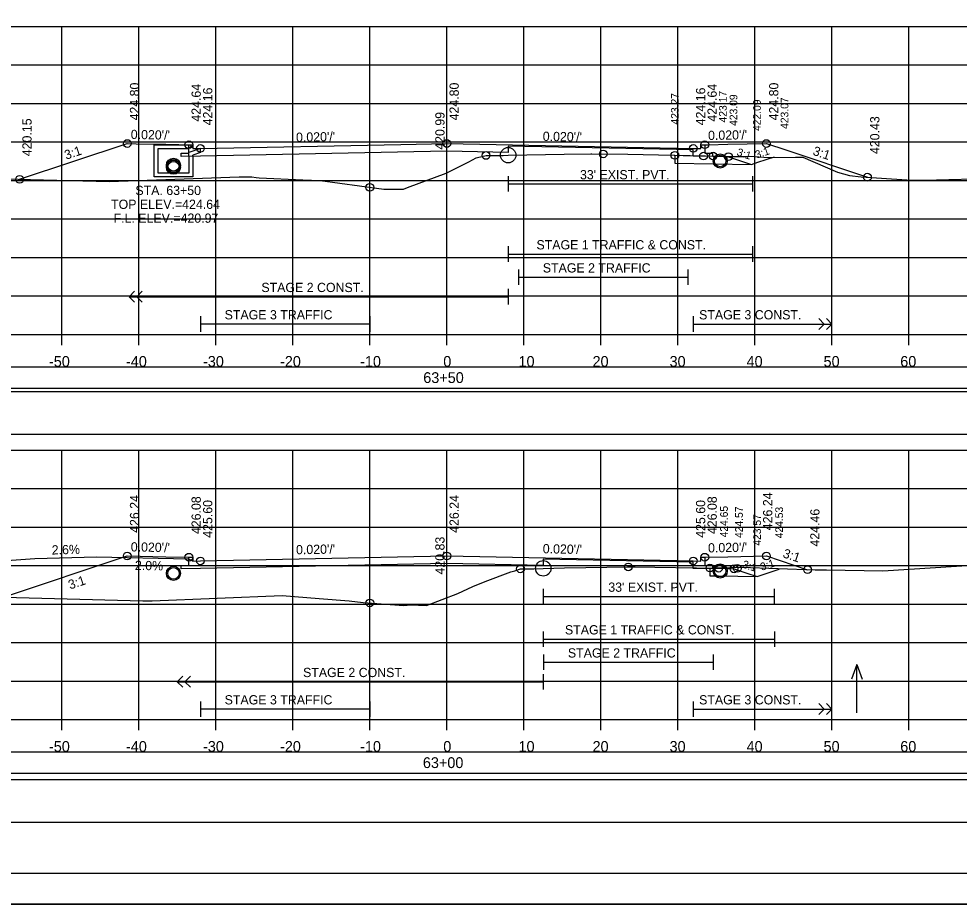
# Model space of a CAD drawing. Extents: x 1371057 to 1372761, y 380005 to 390517.
# Drawn here: x 1371505.3 to 1371627.4, y 385125.2 to 385240.2 of the extents above; entities that cross this region are included whole.
import ezdxf

# ---------------------------------------------------------------- set-up
doc = ezdxf.new("R2010")
doc.units = 0
for name, color, linetype in [('R_Alt Surface', 7, 'Continuous'), ('R_Axis', 7, 'Continuous'), ('R_Axis Annot', 7, 'Continuous'), ('R_Border', 7, 'Continuous'), ('R_Detour', 7, 'Continuous'), ('R_Draft', 7, 'Continuous'), ('R_Drive', 7, 'Continuous'), ('R_Exist Surface', 7, 'Continuous'), ('R_Fin Surface', 7, 'Continuous'), ('R_Fin Surface Annot', 7, 'Continuous'), ('R_Grid', 7, 'Continuous'), ('R_No Plot', 7, 'Continuous'), ('R_Striping', 7, 'Continuous'), ('R_Water', 7, 'Continuous'), ('R_Water Annot', 7, 'Continuous'), ('R_Xsect Elev', 7, 'Continuous'), ('R_Xsect Slope', 7, 'Continuous')]:
    doc.layers.add(name, color=color, linetype=linetype)

msp = doc.modelspace()

# ---------------------------------------------------------------- linework, layer by layer
at = {"layer": 'R_Alt Surface'}
for points in [[(1371594.37, 385223.81), (1371594.37, 385222.73), (1371595.37, 385222.71), (1371595.37, 385222.28), (1371592.87, 385222.33), (1371592.87, 385222.33), (1371592.87, 385223.16), (1371568.84, 385223.64), (1371568.84, 385222.81), (1371560.87, 385222.97), (1371528.87, 385222.33), (1371526.37, 385222.28), (1371526.37, 385222.71), (1371527.37, 385222.73), (1371527.37, 385223.81)], [(1371568.84, 385219.72), (1371568.84, 385217.72)], [(1371568.84, 385218.72), (1371600.58, 385218.72)], [(1371600.58, 385219.72), (1371600.58, 385217.72)], [(1371594.37, 385170.25), (1371594.37, 385169.17), (1371595.37, 385169.15), (1371595.37, 385168.72), (1371592.87, 385168.77), (1371592.87, 385168.77), (1371592.87, 385169.6), (1371573.39, 385169.99), (1371573.39, 385169.16), (1371560.87, 385169.41), (1371528.87, 385168.77), (1371526.37, 385168.72), (1371526.37, 385169.15), (1371527.37, 385169.17), (1371527.37, 385170.25)], [(1371573.39, 385166.15), (1371573.39, 385164.16)], [(1371603.39, 385166.16), (1371603.39, 385164.16)], [(1371573.39, 385165.16), (1371603.39, 385165.16)]]:
    msp.add_lwpolyline(points, dxfattribs=at)
at = {"layer": 'R_Axis'}
for p, q in [((1371410.87, 385199.17), (1371710.87, 385199.17)), ((1371510.87, 385197.77), (1371510.87, 385199.17)), ((1371520.87, 385197.77), (1371520.87, 385199.17)), ((1371530.87, 385197.77), (1371530.87, 385199.17)), ((1371540.87, 385197.77), (1371540.87, 385199.17)), ((1371550.87, 385197.77), (1371550.87, 385199.17)), ((1371560.87, 385197.77), (1371560.87, 385199.17)), ((1371570.87, 385197.77), (1371570.87, 385199.17)), ((1371580.87, 385197.77), (1371580.87, 385199.17)), ((1371590.87, 385197.77), (1371590.87, 385199.17)), ((1371600.87, 385197.77), (1371600.87, 385199.17)), ((1371610.87, 385197.77), (1371610.87, 385199.17)), ((1371620.87, 385197.77), (1371620.87, 385199.17)), ((1371410.87, 385149.17), (1371710.87, 385149.17)), ((1371510.87, 385147.77), (1371510.87, 385149.17)), ((1371520.87, 385147.77), (1371520.87, 385149.17)), ((1371530.87, 385147.77), (1371530.87, 385149.17)), ((1371540.87, 385147.77), (1371540.87, 385149.17)), ((1371550.87, 385147.77), (1371550.87, 385149.17)), ((1371560.87, 385147.77), (1371560.87, 385149.17)), ((1371570.87, 385147.77), (1371570.87, 385149.17)), ((1371580.87, 385147.77), (1371580.87, 385149.17)), ((1371590.87, 385147.77), (1371590.87, 385149.17)), ((1371600.87, 385147.77), (1371600.87, 385149.17)), ((1371610.87, 385147.77), (1371610.87, 385149.17)), ((1371620.87, 385147.77), (1371620.87, 385149.17))]:
    msp.add_line(p, q, dxfattribs=at)
at = {"layer": 'R_Border'}
msp.add_line((1371719.05, 385129.17), (1371402.87, 385129.17), dxfattribs=at)
at = {"layer": 'R_Detour'}
for points in [[(1371590.48, 385222.44), (1371591.56, 385222.42), (1371595.44, 385222.34), (1371596.95, 385222.28), (1371597.44, 385222.26), (1371599.65, 385221.52), (1371600.44, 385221.26), (1371601.25, 385221.53), (1371603.4, 385222.24)], [(1371590.48, 385222.44), (1371590.48, 385221.44), (1371595.44, 385221.34), (1371600.44, 385221.26)], [(1371595.03, 385168.84), (1371595.62, 385168.83), (1371596.16, 385168.82), (1371597.23, 385168.78), (1371598.16, 385168.74), (1371599.84, 385168.18), (1371601.16, 385167.74), (1371602.35, 385168.14), (1371604.02, 385168.7)], [(1371595.03, 385168.84), (1371595.03, 385167.84), (1371596.16, 385167.82), (1371601.16, 385167.74)]]:
    msp.add_lwpolyline(points, dxfattribs=at)
for points in [[(1371407.72, 385192.22), (1371714.03, 385192.22), (1371714.03, 385194.92), (1371407.72, 385194.92)], [(1371407.72, 385142.22), (1371714.03, 385142.22), (1371714.03, 385144.92), (1371407.72, 385144.92)]]:
    msp.add_lwpolyline(points, close=True, dxfattribs=at)
at = {"layer": 'R_Draft'}
for points in [[(1371407.45, 385186.22), (1371713.76, 385186.22), (1371713.76, 385191.74), (1371407.45, 385191.74)], [(1371407.45, 385135.83), (1371713.76, 385135.83), (1371713.76, 385141.35), (1371407.45, 385141.35)]]:
    msp.add_lwpolyline(points, close=True, dxfattribs=at)
at = {"layer": 'R_Drive'}
for p, q in [((1371507.38, 385170.03), (1371499.4, 385169.46)), ((1371515.38, 385170.24), (1371507.38, 385170.03)), ((1371527.38, 385170), (1371515.38, 385170.24)), ((1371527.88, 385169.75), (1371527.38, 385170))]:
    msp.add_line(p, q, dxfattribs=at)
at = {"layer": 'R_Exist Surface'}
for points in [[(1371602.63, 385222.17), (1371606.16, 385222.19), (1371607.11, 385222.19), (1371611.59, 385220.25), (1371613.17, 385219.81), (1371614.65, 385219.66), (1371620.59, 385219.25), (1371622.82, 385219.22), (1371629.29, 385219.4), (1371632.05, 385220.24), (1371633.41, 385220.67), (1371640.68, 385222.44), (1371641.48, 385222.61), (1371641.86, 385222.7), (1371642.14, 385222.77), (1371642.78, 385222.77), (1371650.96, 385224.38), (1371658.47, 385224.69), (1371659.09, 385224.72), (1371660.66, 385224.2), (1371679.54, 385218.13), (1371690.67, 385213.78), (1371698.17, 385210.89), (1371710.87, 385211.41)], [(1371495.46, 385219.59), (1371506.81, 385219.28), (1371517.02, 385219.04), (1371523.15, 385219.26), (1371533.92, 385219.65), (1371535.53, 385219.66), (1371536.1, 385219.54), (1371536.48, 385219.53), (1371542.19, 385219.26), (1371544.42, 385219.18), (1371549.51, 385218.46), (1371552.68, 385218.04), (1371555.13, 385218.05), (1371555.26, 385218.05), (1371555.75, 385218.24), (1371560.79, 385220.12), (1371563.72, 385221.59), (1371564.66, 385222.09), (1371564.87, 385222.14), (1371565.96, 385222.42), (1371568.2, 385222.43), (1371568.84, 385222.46), (1371568.84, 385222.46), (1371576.11, 385222.59), (1371579.55, 385222.65), (1371579.69, 385222.64), (1371584.39, 385222.57), (1371588.37, 385222.49), (1371590.41, 385222.44), (1371590.48, 385222.44), (1371594.46, 385222.35), (1371597.49, 385222.29), (1371598.66, 385222.28), (1371599.33, 385222.29), (1371599.79, 385222.3), (1371600.12, 385222.31), (1371602.63, 385222.17)], [(1371498.4, 385165.18), (1371521.41, 385164.58), (1371521.98, 385164.57), (1371522.6, 385164.59), (1371539.49, 385165.26), (1371544.31, 385164.88), (1371548.2, 385164.57), (1371550, 385164.38), (1371555.3, 385163.98), (1371556.15, 385164.05), (1371558.23, 385163.96), (1371562.29, 385165.55), (1371564.26, 385166.45), (1371565.84, 385167.08), (1371569.19, 385168.37), (1371569.7, 385168.5), (1371570.43, 385168.73), (1371572.16, 385168.76), (1371573.39, 385168.8), (1371576.17, 385168.87), (1371578.9, 385168.93), (1371581.66, 385168.96), (1371584.33, 385168.99), (1371584.8, 385168.99), (1371585.33, 385169), (1371587.86, 385168.97), (1371593.31, 385168.88), (1371595.03, 385168.84), (1371595.96, 385168.85), (1371597.77, 385168.9), (1371599.07, 385168.95), (1371608.71, 385168.61)], [(1371608.71, 385168.61), (1371610.18, 385168.63), (1371617.47, 385168.49), (1371630.48, 385169.28), (1371631.66, 385169.24), (1371633.04, 385169.17), (1371638.13, 385168.94), (1371647.78, 385168.58), (1371650.08, 385168.63), (1371655.66, 385169.36), (1371656.54, 385169.38), (1371660.65, 385169.25), (1371661.37, 385169.24), (1371663.65, 385169.3), (1371667.81, 385169.06), (1371671.71, 385169.15), (1371676.71, 385168.26), (1371691.54, 385164.97), (1371697.83, 385163.65), (1371700.11, 385163.72), (1371710.87, 385164.54)]]:
    msp.add_lwpolyline(points, dxfattribs=at)
at = {"layer": 'R_Fin Surface'}
for points in [[(1371505.4, 385219.32), (1371519.37, 385223.97), (1371520.53, 385223.95), (1371524.37, 385223.87), (1371526.08, 385223.84), (1371527.37, 385223.81), (1371527.87, 385223.81), (1371527.88, 385223.31), (1371528.25, 385223.32), (1371528.87, 385223.33), (1371528.87, 385223.33), (1371554.9, 385223.85), (1371560.87, 385223.97), (1371592.87, 385223.33), (1371593.78, 385223.31), (1371593.87, 385223.31), (1371593.87, 385223.81), (1371594.37, 385223.81), (1371594.87, 385223.82), (1371597.37, 385223.87), (1371602.37, 385223.97), (1371604.91, 385223.13), (1371615.49, 385219.6)], [(1371503.31, 385165.06), (1371519.37, 385170.41), (1371524.37, 385170.31), (1371527.37, 385170.25), (1371527.53, 385170.25), (1371527.87, 385170.25), (1371527.88, 385169.75), (1371528.87, 385169.77), (1371560.87, 385170.41), (1371560.87, 385170.41), (1371560.87, 385170.41), (1371592.87, 385169.77), (1371593.87, 385169.75), (1371593.87, 385170.25), (1371593.97, 385170.25), (1371594.37, 385170.25), (1371597.37, 385170.31), (1371602.37, 385170.41), (1371607.71, 385168.63)]]:
    msp.add_lwpolyline(points, dxfattribs=at)
at = {"layer": 'R_Grid'}
for p, q in [((1371410.87, 385239.17), (1371710.87, 385239.17)), ((1371510.87, 385199.17), (1371510.87, 385239.17)), ((1371520.87, 385199.17), (1371520.87, 385239.17)), ((1371530.87, 385199.17), (1371530.87, 385239.17)), ((1371540.87, 385199.17), (1371540.87, 385239.17)), ((1371550.87, 385199.17), (1371550.87, 385239.17)), ((1371560.87, 385199.17), (1371560.87, 385239.17)), ((1371570.87, 385199.17), (1371570.87, 385239.17)), ((1371580.87, 385199.17), (1371580.87, 385239.17)), ((1371590.87, 385199.17), (1371590.87, 385239.17)), ((1371600.87, 385199.17), (1371600.87, 385239.17)), ((1371610.87, 385199.17), (1371610.87, 385239.17)), ((1371620.87, 385199.17), (1371620.87, 385239.17)), ((1371410.87, 385234.17), (1371710.87, 385234.17)), ((1371410.87, 385229.17), (1371710.87, 385229.17)), ((1371410.87, 385224.17), (1371710.87, 385224.17)), ((1371410.87, 385219.17), (1371710.87, 385219.17)), ((1371410.87, 385214.17), (1371710.87, 385214.17)), ((1371410.87, 385209.17), (1371710.87, 385209.17)), ((1371410.87, 385204.17), (1371710.87, 385204.17)), ((1371410.87, 385199.17), (1371710.87, 385199.17)), ((1371410.87, 385184.17), (1371710.87, 385184.17)), ((1371510.87, 385149.17), (1371510.87, 385184.17)), ((1371520.87, 385149.17), (1371520.87, 385184.17)), ((1371530.87, 385149.17), (1371530.87, 385184.17)), ((1371540.87, 385149.17), (1371540.87, 385184.17)), ((1371550.87, 385149.17), (1371550.87, 385184.17)), ((1371560.87, 385149.17), (1371560.87, 385184.17)), ((1371570.87, 385149.17), (1371570.87, 385184.17)), ((1371580.87, 385149.17), (1371580.87, 385184.17)), ((1371590.87, 385149.17), (1371590.87, 385184.17)), ((1371600.87, 385149.17), (1371600.87, 385184.17)), ((1371610.87, 385149.17), (1371610.87, 385184.17)), ((1371620.87, 385149.17), (1371620.87, 385184.17)), ((1371410.87, 385179.17), (1371710.87, 385179.17)), ((1371410.87, 385174.17), (1371710.87, 385174.17)), ((1371410.87, 385169.17), (1371710.87, 385169.17)), ((1371410.87, 385164.17), (1371710.87, 385164.17)), ((1371410.87, 385159.17), (1371710.87, 385159.17)), ((1371410.87, 385154.17), (1371710.87, 385154.17)), ((1371410.87, 385149.17), (1371710.87, 385149.17))]:
    msp.add_line(p, q, dxfattribs=at)
at = {"layer": 'R_No Plot'}
msp.add_line((1371390.47, 385125.19), (1371723.8, 385125.19), dxfattribs=at)
for points in [[(1371390.46, 385338.53), (1371723.8, 385338.53), (1371723.8, 385125.19), (1371390.46, 385125.19)], [(1371636.79, 385334.63), (1371656.41, 385334.63), (1371656.41, 385324.75), (1371672.52, 385324.75), (1371695.72, 385324.75), (1371695.84, 385296.59), (1371719.05, 385296.59), (1371719.05, 385129.17), (1371402.87, 385129.17), (1371402.87, 385334.63)]]:
    msp.add_lwpolyline(points, close=True, dxfattribs=at)
for centre, radius in [((1371519.37, 385223.97), 0.5), ((1371527.37, 385223.81), 0.5), ((1371528.87, 385223.33), 0.5), ((1371560.87, 385223.97), 0.5), ((1371592.87, 385223.33), 0.5), ((1371594.37, 385223.81), 0.5), ((1371602.37, 385223.97), 0.5), ((1371565.96, 385222.42), 0.5), ((1371568.84, 385222.46), 1), ((1371581.18, 385222.62), 0.5), ((1371590.48, 385222.44), 0.5), ((1371594.2, 385222.34), 0.5), ((1371595.44, 385222.34), 0.5), ((1371596.37, 385221.7), 0.917), ((1371597.44, 385222.26), 0.5), ((1371525.37, 385221.14), 0.917), ((1371525.37, 385220.89), 0.917), ((1371615.49, 385219.6), 0.5), ((1371505.4, 385219.32), 0.5), ((1371550.87, 385218.28), 0.5), ((1371519.37, 385170.41), 0.5), ((1371527.37, 385170.25), 0.5), ((1371528.87, 385169.77), 0.5), ((1371560.87, 385170.41), 0.5), ((1371592.87, 385169.77), 0.5), ((1371594.37, 385170.25), 0.5), ((1371602.37, 385170.41), 0.5), ((1371525.37, 385168.15), 0.917), ((1371570.43, 385168.73), 0.5), ((1371573.39, 385168.8), 1), ((1371584.44, 385168.99), 0.5), ((1371595.03, 385168.84), 0.5), ((1371596.37, 385168.45), 0.917), ((1371596.16, 385168.82), 0.5), ((1371598.16, 385168.74), 0.5), ((1371598.59, 385168.79), 0.5), ((1371607.71, 385168.63), 0.5), ((1371550.87, 385164.31), 0.5)]:
    msp.add_circle(centre, radius, dxfattribs=at)
at = {"layer": 'R_Striping'}
for p, q in [((1371568.84, 385210.62), (1371568.84, 385208.62)), ((1371600.58, 385210.62), (1371600.58, 385208.62)), ((1371568.84, 385209.62), (1371600.58, 385209.62)), ((1371570.18, 385207.62), (1371570.18, 385205.62)), ((1371570.18, 385206.62), (1371592.18, 385206.62)), ((1371592.18, 385207.62), (1371592.18, 385205.62)), ((1371519.6, 385204.08), (1371520.31, 385204.78)), ((1371519.6, 385204.08), (1371568.84, 385204.08)), ((1371520.31, 385203.37), (1371519.6, 385204.08)), ((1371520.6, 385204.08), (1371521.31, 385204.78)), ((1371521.31, 385203.37), (1371520.6, 385204.08)), ((1371568.84, 385205.08), (1371568.84, 385203.08)), ((1371528.87, 385201.53), (1371528.87, 385199.53)), ((1371550.87, 385200.53), (1371528.87, 385200.53)), ((1371550.87, 385201.53), (1371550.87, 385199.53)), ((1371592.87, 385201.53), (1371592.87, 385199.53)), ((1371592.87, 385200.53), (1371610.87, 385200.53)), ((1371609.87, 385200.53), (1371609.17, 385201.24)), ((1371609.17, 385199.83), (1371609.87, 385200.53)), ((1371610.87, 385200.53), (1371610.17, 385201.24)), ((1371610.17, 385199.83), (1371610.87, 385200.53)), ((1371573.39, 385160.62), (1371573.39, 385158.62)), ((1371603.42, 385160.62), (1371603.42, 385158.62)), ((1371573.39, 385159.62), (1371603.42, 385159.62)), ((1371573.44, 385157.62), (1371573.44, 385155.62)), ((1371595.44, 385157.62), (1371595.44, 385155.62)), ((1371573.44, 385156.62), (1371595.44, 385156.62)), ((1371525.87, 385154.08), (1371526.57, 385154.78)), ((1371525.87, 385154.08), (1371573.39, 385154.08)), ((1371526.57, 385153.37), (1371525.87, 385154.08)), ((1371526.87, 385154.08), (1371527.57, 385154.78)), ((1371527.57, 385153.37), (1371526.87, 385154.08)), ((1371573.39, 385155.08), (1371573.39, 385153.08)), ((1371528.87, 385151.53), (1371528.87, 385149.53)), ((1371550.87, 385151.53), (1371550.87, 385149.53)), ((1371592.87, 385151.53), (1371592.87, 385149.53)), ((1371550.87, 385150.53), (1371528.87, 385150.53)), ((1371592.87, 385150.53), (1371610.87, 385150.53)), ((1371609.87, 385150.53), (1371609.17, 385151.24)), ((1371609.17, 385149.83), (1371609.87, 385150.53)), ((1371610.87, 385150.53), (1371610.17, 385151.24)), ((1371610.17, 385149.83), (1371610.87, 385150.53))]:
    msp.add_line(p, q, dxfattribs=at)
at = {"layer": 'R_Water'}
for p, q in [((1371522.87, 385223.81), (1371527.62, 385223.81)), ((1371522.87, 385222.31), (1371522.87, 385223.81)), ((1371527.7, 385223.65), (1371527.37, 385223.31)), ((1371527.7, 385223.65), (1371527.62, 385223.81)), ((1371523.37, 385222.31), (1371523.37, 385223.31)), ((1371523.37, 385223.31), (1371527.37, 385223.31)), ((1371528.87, 385223.33), (1371527.37, 385222.81)), ((1371527.37, 385222.31), (1371527.37, 385222.81)), ((1371528.87, 385222.8), (1371527.87, 385222.46)), ((1371527.87, 385222.31), (1371527.87, 385222.46))]:
    msp.add_line(p, q, dxfattribs=at)
for points in [[(1371528.87, 385222.8), (1371528.87, 385223.33)], [(1371527.87, 385222.31), (1371527.87, 385219.64), (1371525.37, 385219.64), (1371522.87, 385219.64), (1371522.87, 385222.31)], [(1371527.37, 385222.31), (1371527.37, 385220.14), (1371525.37, 385220.14), (1371523.37, 385220.14), (1371523.37, 385222.31)]]:
    msp.add_lwpolyline(points, dxfattribs=at)
for centre in [(1371596.37, 385221.7), (1371525.37, 385221.14), (1371525.37, 385220.89), (1371525.37, 385168.15), (1371596.37, 385168.45)]:
    msp.add_circle(centre, 0.75, dxfattribs=at)
at = {"layer": 'R_Water Annot'}
for p, q in [((1371614.11, 385156.32), (1371613.41, 385154.4)), ((1371614.11, 385150.04), (1371614.11, 385156.32)), ((1371614.11, 385156.32), (1371614.81, 385154.4))]:
    msp.add_line(p, q, dxfattribs=at)
at = {"layer": 'R_Xsect Elev'}
for p, q in [((1371560.87, 385220.16), (1371560.87, 385230.16)), ((1371560.87, 385165), (1371560.87, 385175))]:
    msp.add_line(p, q, dxfattribs=at)

# ---------------------------------------------------------------- texts
at = {"layer": 'R_Axis Annot'}
for s, p in [('-50', (1371509.21, 385194.97)), ('-40', (1371519.21, 385194.97)), ('-30', (1371529.21, 385194.97)), ('-20', (1371539.21, 385194.97)), ('-10', (1371549.61, 385194.97)), ('0', (1371560.41, 385194.97)), ('10', (1371570.18, 385194.97)), ('20', (1371579.79, 385194.97)), ('30', (1371589.79, 385194.97)), ('40', (1371599.79, 385194.97)), ('50', (1371609.79, 385194.97)), ('60', (1371619.75, 385194.97)), ('63+50', (1371557.81, 385192.87)), ('-50', (1371509.21, 385144.97)), ('-40', (1371519.21, 385144.97)), ('-30', (1371529.21, 385144.97)), ('-20', (1371539.21, 385144.97)), ('-10', (1371549.61, 385144.97)), ('0', (1371560.41, 385144.97)), ('10', (1371570.18, 385144.97)), ('20', (1371579.79, 385144.97)), ('30', (1371589.79, 385144.97)), ('40', (1371599.79, 385144.97)), ('50', (1371609.79, 385144.97)), ('60', (1371619.75, 385144.97)), ('63+00', (1371557.76, 385142.87))]:
    msp.add_text(s, height=1.4, dxfattribs=at).set_placement(p)
at = {"layer": 'R_Fin Surface Annot'}
for s, rotation, p in [('423.27', 90, (1371590.98, 385226.44)), ('423.17', 90, (1371597.21, 385226.71)), ('423.09', 90, (1371598.59, 385226.26)), ('423.07', 90, (1371605.22, 385225.87)), ('422.09', 90, (1371601.64, 385225.6)), ('3:1', 341.546, (1371598.44, 385222.45)), ('3:1', 18.407, (1371601.1, 385222.01)), ('424.65', 90, (1371597.36, 385172.82)), ('424.57', 90, (1371599.31, 385172.74)), ('424.53', 90, (1371604.52, 385172.7)), ('423.57', 90, (1371601.66, 385171.74)), ('3:1', 341.6649, (1371599.16, 385168.93)), ('3:1', 18.497, (1371601.77, 385168.48))]:
    msp.add_text(s, height=1, rotation=rotation, dxfattribs=at).set_placement(p)
at = {"layer": 'R_Striping'}
for s, p in [('STAGE 1 TRAFFIC & CONST.', (1371572.51, 385210.22)), ('STAGE 2 TRAFFIC', (1371573.33, 385207.22)), ('STAGE 2 CONST.', (1371536.79, 385204.68)), ('STAGE 3 TRAFFIC', (1371532.02, 385201.13)), ('STAGE 3 CONST.', (1371593.63, 385201.13)), ('STAGE 1 TRAFFIC & CONST.', (1371576.21, 385160.22)), ('STAGE 2 TRAFFIC', (1371576.59, 385157.22)), ('STAGE 2 CONST.', (1371542.2, 385154.68)), ('STAGE 3 TRAFFIC', (1371532.02, 385151.13)), ('STAGE 3 CONST.', (1371593.63, 385151.13))]:
    msp.add_text(s, height=1.2, dxfattribs=at).set_placement(p)
at = {"layer": 'R_Water'}
for p in [(1371578.16, 385219.32), (1371581.84, 385165.76)]:
    msp.add_text("33' EXIST. PVT.", height=1.2, dxfattribs=at).set_placement(p)
at = {"layer": 'R_Water Annot'}
for s, p in [('STA. 63+50', (1371520.43, 385217.28)), ('TOP ELEV.=424.64', (1371517.27, 385215.48)), ('F.L. ELEV.=420.97', (1371517.6, 385213.68))]:
    msp.add_text(s, height=1.2, dxfattribs=at).set_placement(p)
at = {"layer": 'R_Xsect Elev'}
for s, rotation, p in [('424.80', 90, (1371520.92, 385226.97)), ('424.64', 90, (1371528.92, 385226.81)), ('424.16', 90, (1371530.42, 385226.33)), ('424.80', 90, (1371562.42, 385226.97)), ('424.16', 90, (1371594.42, 385226.33)), ('424.64', 90, (1371595.92, 385226.81)), ('424.80', 90, (1371603.92, 385226.97)), ('420.99', 90, (1371560.57, 385223.16)), ('420.43', 90, (1371617.04, 385222.6)), ('420.15', 90, (1371506.95, 385222.32)), ('426.24', 90, (1371603.13, 385173.75)), ('426.24', 90, (1371520.92, 385173.41)), ('426.08', 90, (1371528.92, 385173.25)), ('425.60', 90, (1371530.42, 385172.77)), ('426.24', 90, (1371562.42, 385173.41)), ('425.60', 90, (1371594.42, 385172.77)), ('426.08', 90, (1371595.92, 385173.25)), ('424.46', 90, (1371609.26, 385171.63)), ('420.83', 90, (1371560.57, 385168)), ('2.6%', 1.4894, (1371509.58, 385170.59)), ('2.0%', 358.8542, (1371520.36, 385168.6))]:
    msp.add_text(s, height=1.2, rotation=rotation, dxfattribs=at).set_placement(p)
at = {"layer": 'R_Xsect Slope'}
for s, rotation, p in [("0.020'/'", 358.8543, (1371519.82, 385224.56)), ("0.020'/'", 1.1458, (1371541.3, 385224.18)), ("0.020'/'", 358.8542, (1371573.32, 385224.32)), ("0.020'/'", 1.1457, (1371594.8, 385224.42)), ('3:1', 18.4321, (1371511.44, 385221.86)), ('3:1', 341.5644, (1371608.3, 385222.52)), ("0.020'/'", 358.8541, (1371519.82, 385171)), ("0.020'/'", 1.1458, (1371541.3, 385170.62)), ("0.020'/'", 358.8542, (1371573.32, 385170.76)), ("0.020'/'", 1.1457, (1371594.8, 385170.86)), ('3:1', 341.5605, (1371604.41, 385170.26)), ('3:1', 18.4352, (1371511.95, 385166.05))]:
    msp.add_text(s, height=1.2, rotation=rotation, dxfattribs=at).set_placement(p)

doc.saveas('drawing.dxf')
